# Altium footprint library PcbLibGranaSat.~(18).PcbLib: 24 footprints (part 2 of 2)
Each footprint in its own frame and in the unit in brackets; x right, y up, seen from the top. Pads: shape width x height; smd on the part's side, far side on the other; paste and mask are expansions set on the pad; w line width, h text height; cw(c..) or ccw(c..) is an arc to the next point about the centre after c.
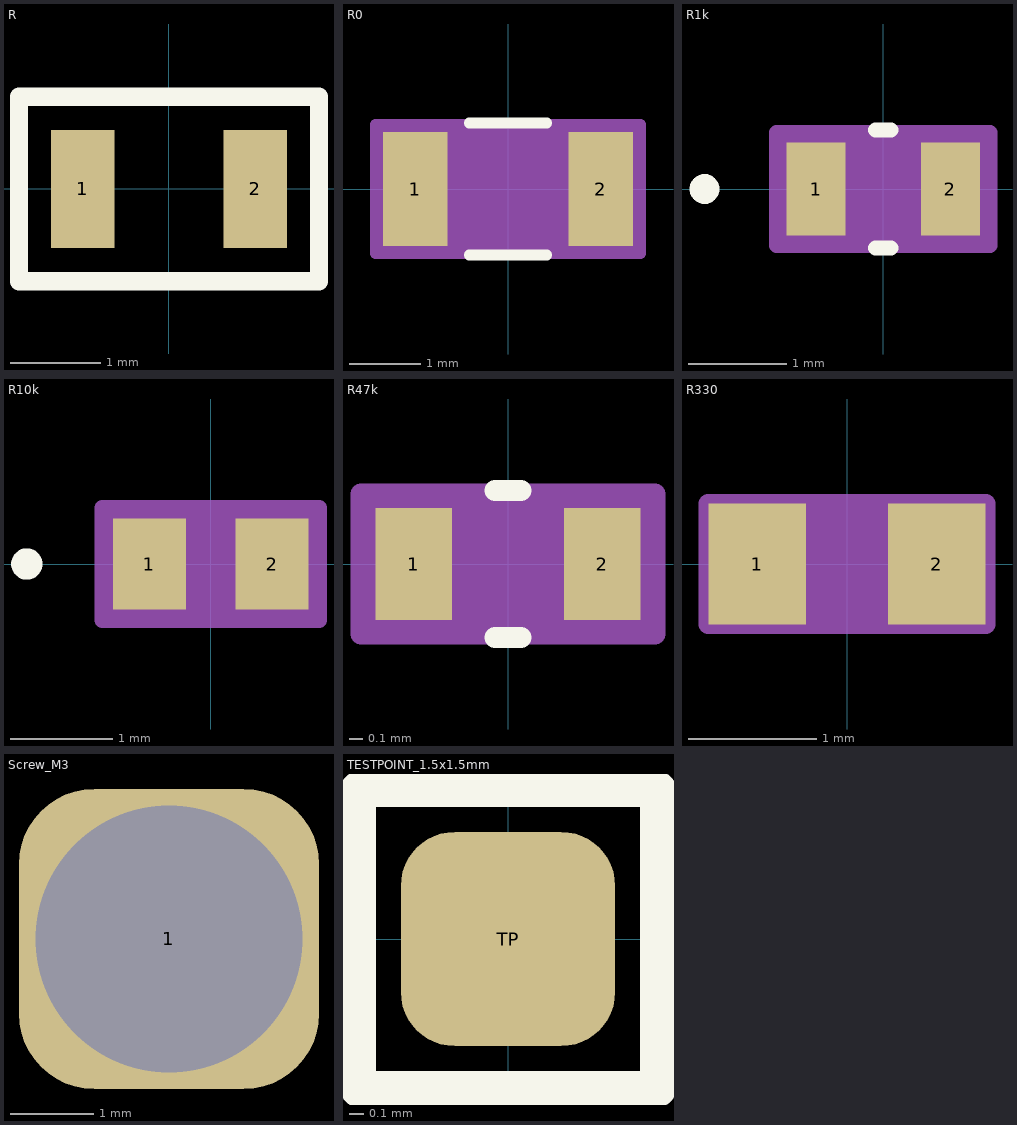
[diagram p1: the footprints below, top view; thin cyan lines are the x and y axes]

## R [mm]
pads (2):
  rect 0.7x1.3 smd: 1(-0.95,0) 2(0.95,0)
Top Overlay:
  lines w0.2: -1.651,-1.016 -1.651,0.483 -1.651,1.016 1.651,1.016 1.651,-1.016 -1.651,-1.016

## R0 [mm]
pads (2):
  rect 0.902x1.6 smd paste+0 mask+0: 1(-1.301,0) 2(1.301,0)
Top Overlay:
  lines w0.152: -0.542,-0.927 0.542,-0.927 ; -0.542,0.927 0.542,0.927
Mechanical 13:
  lines w0.025: -1.6,-0.8 -1.6,0.8 ; -1.6,-0.8 -0.85,-0.8 -0.85,0.8 -1.6,0.8 ; -1.6,-0.8 1.6,-0.8 ; -1.6,-0.8 -1.6,0.8 ; -1.6,0.8 1.6,0.8 ; 1.6,-0.8 0.85,-0.8 0.85,0.8 1.6,0.8 ; 1.6,-0.8 1.6,0.8 ; 1.6,-0.8 1.6,0.8
Mechanical 15:
  region: 1.854,-0.902 -1.854,-0.902 -1.854,0.902 1.854,0.902
  lines w0.152: -1.854,-0.902 -1.854,0.902 1.854,0.902 1.854,-0.902 -1.854,-0.902
3D body: height 0.25, standoff 0, extent 0,0 0.254,0.254

## R1k [mil]
pads (2):
  rect 23.68x37.4 smd paste+0 mask+0: 1(-27,0) 2(27,0)
Top Overlay:
  circle w6: c-71.84,0 r3
  lines w6: -3.05,-23.7 3.05,-23.7 ; -3.05,23.7 3.05,23.7
Mechanical 13:
  circle w0: c-22,0 r3
  lines w1: -34.84,-18.7 -34.84,18.7 ; -34.84,-18.7 -15.16,-18.7 -15.16,18.7 -34.84,18.7 ; -34.84,-18.7 34.84,-18.7 ; -34.84,-18.7 -34.84,18.7 ; -34.84,18.7 34.84,18.7 ; 34.84,-18.7 15.16,-18.7 15.16,18.7 34.84,18.7 ; 34.84,-18.7 34.84,18.7 ; 34.84,-18.7 34.84,18.7
Mechanical 15:
  region: 42.84,-22.7 -42.84,-22.7 -42.84,22.7 42.84,22.7
  lines w6: -42.84,-22.7 -42.84,22.7 42.84,22.7 42.84,-22.7 -42.84,-22.7
3D body: height 10, standoff 0, extent 0,0 10,10

## R10k [mil]
pads (2):
  rect 28x35 smd paste+0 mask+0: 1(-23.5,0) 2(23.5,0)
Top Overlay:
  circle w6: c-70.5,0 r3
Mechanical 13:
  circle w0: c-18.5,0 r3
  lines w1: -33.5,-17.5 -33.5,17.5 ; -33.5,-17.5 33.5,-17.5 ; -33.5,-17.5 -9.5,-17.5 -9.5,17.5 -33.5,17.5 ; -33.5,-17.5 -33.5,17.5 ; -33.5,17.5 33.5,17.5 ; 33.5,-17.5 33.5,17.5 ; 33.5,-17.5 33.5,17.5 ; 33.5,-17.5 9.5,-17.5 9.5,17.5 33.5,17.5
Mechanical 15:
  region: 41.5,-21.5 -41.5,-21.5 -41.5,21.5 41.5,21.5
  lines w6: -41.5,-21.5 41.5,-21.5 41.5,21.5 -41.5,21.5 -41.5,-21.5
3D body: height 10, standoff 0, extent 0,0 10,10

## R47k [mm]
pads (2):
  rect 0.552x0.8 smd paste+0 mask+0: 1(-0.676,0) 2(0.676,0)
Top Overlay:
  lines w0.152: -0.092,-0.527 0.092,-0.527 ; -0.092,0.527 0.092,0.527
Mechanical 13:
  lines w0.025: -0.8,-0.4 -0.8,0.4 ; -0.8,-0.4 -0.4,-0.4 -0.4,0.4 -0.8,0.4 ; -0.8,-0.4 0.8,-0.4 ; -0.8,-0.4 -0.8,0.4 ; -0.8,0.4 0.8,0.4 ; 0.8,-0.4 0.4,-0.4 0.4,0.4 0.8,0.4 ; 0.8,-0.4 0.8,0.4 ; 0.8,-0.4 0.8,0.4
Mechanical 15:
  region: 1.054,-0.502 -1.054,-0.502 -1.054,0.502 1.054,0.502
  lines w0.152: -1.054,-0.502 -1.054,0.502 1.054,0.502 1.054,-0.502 -1.054,-0.502
3D body: height 0.25, standoff 0, extent 0,0 0.254,0.254

## R330 [mil]
pads (2):
  rect 30x37 smd paste+0 mask+0: 1(-27.5,0) 2(27.5,0)
Mechanical 13:
  lines w1: -32.5,-18.5 32.5,-18.5 32.5,18.5 -32.5,18.5 -32.5,-18.5
Mechanical 15:
  region: -32.5,-18.5 -42.5,-18.5 -42.5,18.5 -32.5,18.5 32.5,18.5 42.5,18.5 42.5,-18.5 32.5,-18.5
  lines w6: -42.5,-18.5 -42.5,18.5 -32.5,18.5 32.5,18.5 42.5,18.5 42.5,-18.5 32.5,-18.5 -32.5,-18.5 -42.5,-18.5
3D body: height 10, standoff 0, extent 0,0 10,10

## Screw_M3 [mm] "Main CubeSAT bus M3 screw"
pads (1):
  rrect50% 3.6x3.6 hole 3.2: 1(72.04,27.44)

## TESTPOINT_1.5x1.5mm [mm] "Punto de test de 1.5x1.5mm"
pads (1):
  rrect50% 1.5x1.5 smd: TP(0,0)
Top Overlay:
  lines w0.254: -1.05,-1.05 -1.05,1.05 1.05,1.05 1.05,-1.05 -1.05,-1.05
